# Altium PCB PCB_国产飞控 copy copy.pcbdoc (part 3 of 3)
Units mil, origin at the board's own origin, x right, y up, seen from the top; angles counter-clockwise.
Board outline 2782.5 x 2450 mil, 4 copper layers (Top Layer, Inner1, Inner2, Bottom Layer), stack 2.757 mil thick; 92 components, 104 nets, 474 pads, 149 vias.
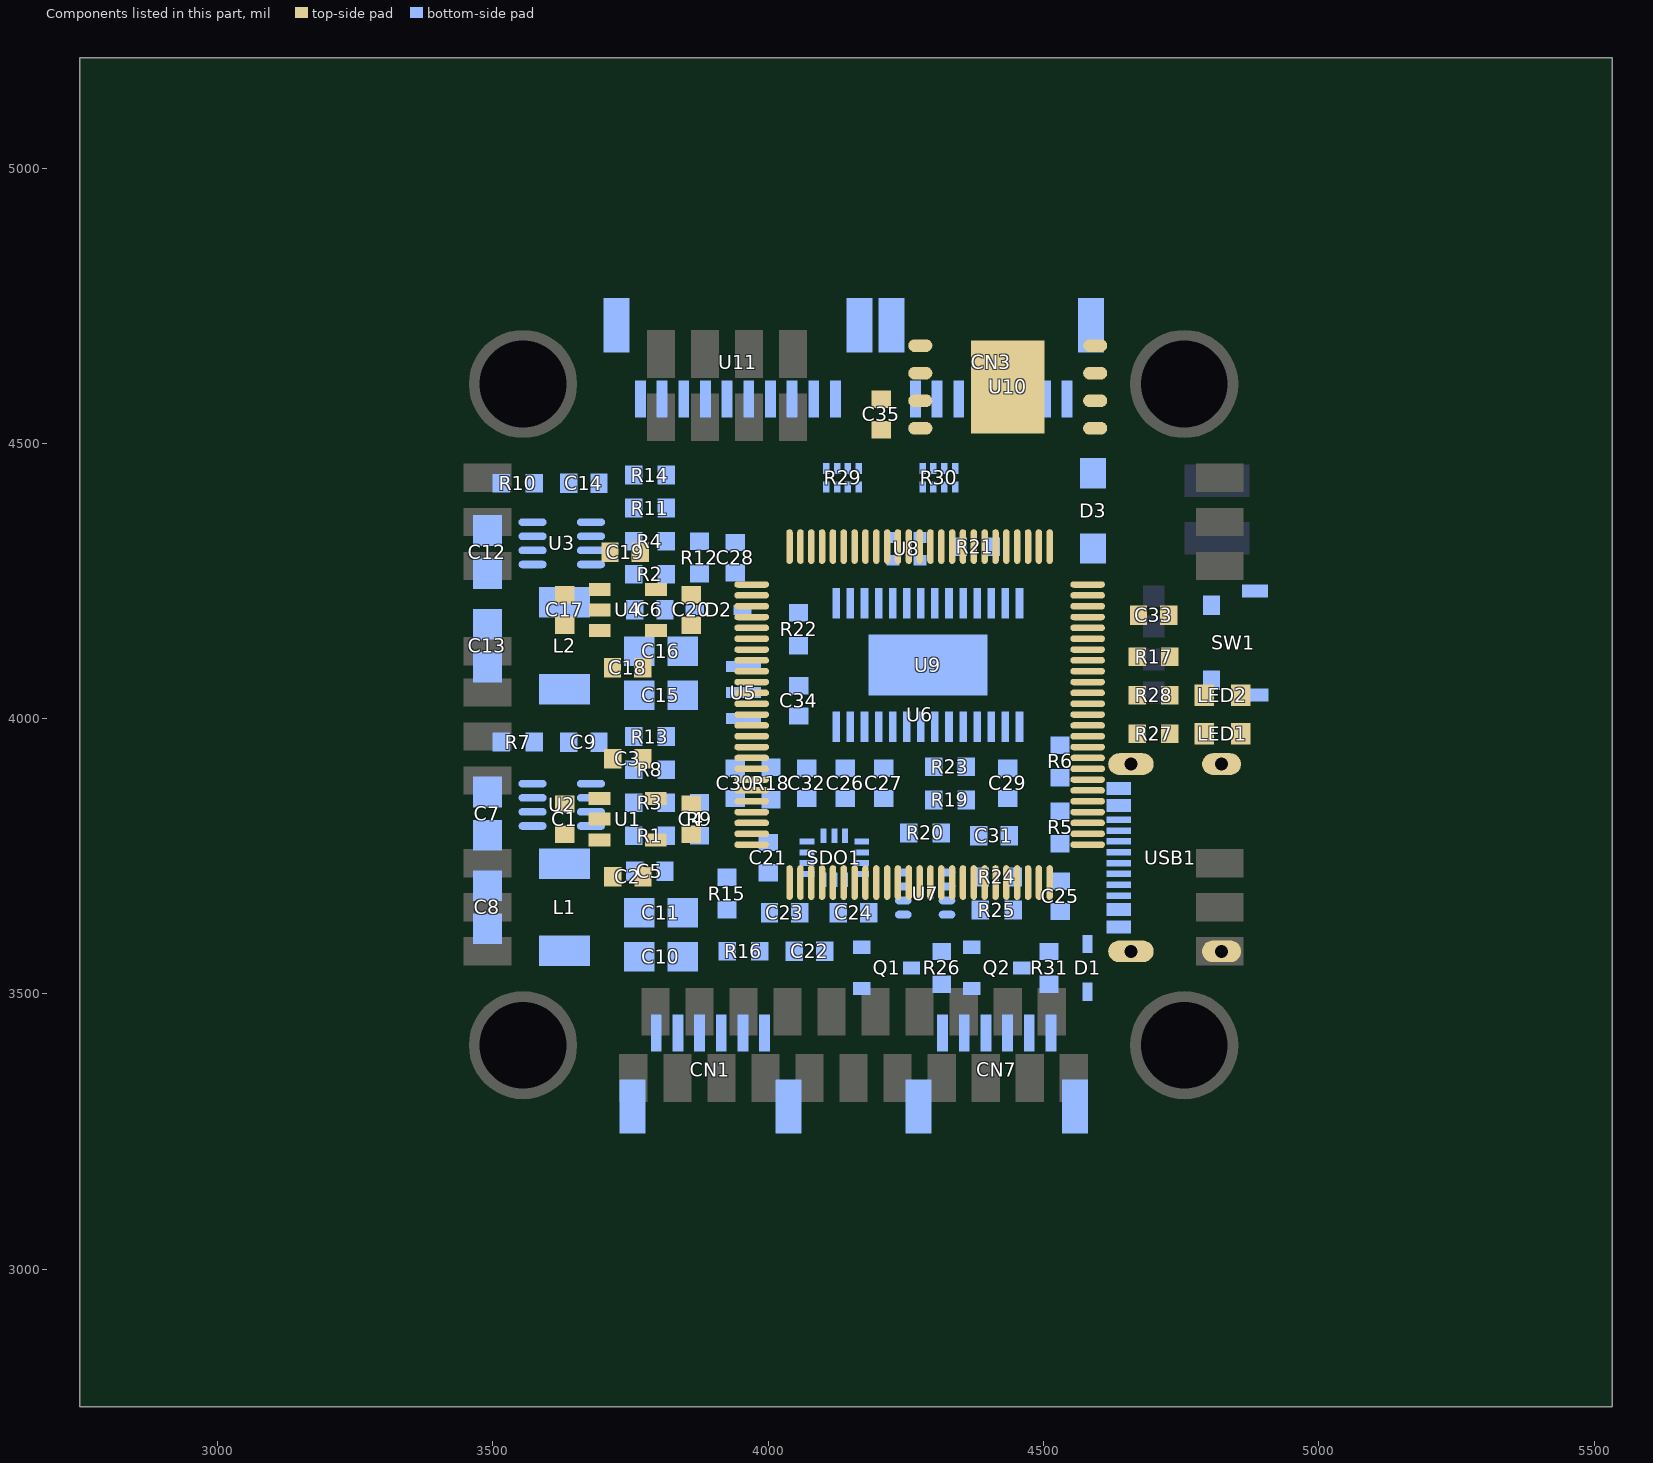
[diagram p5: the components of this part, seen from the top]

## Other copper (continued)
Inner2:
  region net SERVO2: 4358.07,4368.35 4358.07,4386.65 4366.62,4382.5 4366.62,4372.5
  region net SERVO1: 4398.07,4408.35 4398.07,4426.65 4406.62,4422.5 4406.62,4412.5
  region net GYRO_EXTI1: 4195.85,3760.57 4214.15,3760.57 4210,3769.12 4200,3769.12
  region net GYRO_EXTI1: 4490.76,4245.32 4477.82,4258.26 4474.71,4249.29 4481.79,4242.21
  region net +10V: 3757.18,3506.74 3744.24,3519.68 3749.43,3523.07 3760.57,3511.93
  region net UART4_RX: 3915.76,3794.68 3902.82,3781.74 3899.71,3790.71 3906.79,3797.79
  region net UART4_RX: 3880.76,4390.32 3867.82,4403.26 3864.71,4394.29 3871.79,4387.21
  region net 3V3-IMU: 3982.18,3718.26 3969.24,3705.32 3978.21,3702.21 3985.29,3709.29
  region net SERVO2: 4537.18,4031.74 4524.24,4044.68 4533.21,4047.79 4540.29,4040.71
  region net SERVO1: 4630.76,4029.68 4617.82,4016.74 4614.71,4025.71 4621.79,4032.79
  region net UART1_RX: 4642.18,4113.26 4629.24,4100.32 4638.21,4097.21 4645.29,4104.29
  region net UART1_TX: 4525.76,4105.32 4512.82,4118.26 4509.71,4109.29 4516.79,4102.21
  region net VBAT_ADC: 4220.76,3579.68 4207.82,3566.74 4206.46,3573.96 4213.54,3581.04
  region net VBAT_ADC: 3962.18,3613.26 3949.24,3600.32 3958.21,3597.21 3965.29,3604.29
  region net CURRENT1: 4260.76,3629.68 4247.82,3616.74 4244.71,3625.71 4251.79,3632.79
  region net CURRENT1: 3798.07,4468.35 3798.07,4486.65 3806.62,4482.5 3806.62,4472.5
  region net +10V: 3748.07,4623.35 3748.07,4641.65 3755,4640.37 3755,4624.63
  region net VDD: 4685.85,4250.57 4704.15,4250.57 4700,4259.12 4690,4259.12
  region net VDD: 4620.85,4644.43 4639.15,4644.43 4635,4635.88 4625,4635.88
  region net LED: 3540.85,4229.43 3559.15,4229.43 3555,4220.88 3545,4220.88
  region net LED: 3540.85,3775.57 3559.15,3775.57 3555,3784.12 3545,3784.12
  region net +5V: 4025.85,4724.43 4044.15,4724.43 4042.87,4715.88 4027.13,4715.88
  region net +5V: 4090.85,4170.57 4109.15,4170.57 4107.87,4179.12 4092.13,4179.12
  region net +5V: 3655.85,3925.57 3674.15,3925.57 3672.87,3934.12 3657.13,3934.12
  region net +5V: 4530.23,4210.62 4511.93,4210.67 4516.06,4219.2 4526.14,4219.17
  region net +5V: 3713.25,4152.03 3731.55,4152.03 3730.27,4143.48 3714.53,4143.48
  region net 3V3-IMU: 4195.76,3629.68 4182.82,3616.74 4179.71,3625.71 4186.79,3632.79
  region net UART1_RX: 4265.85,3539.43 4284.15,3539.43 4280,3530.88 4270,3530.88
  region net UART1_TX: 4126.74,3464.16 4116.85,3479.56 4126.21,3480.79 4131.75,3472.18
  region net UART1_RX: 4207.18,3466.74 4194.24,3479.68 4203.21,3482.79 4210.29,3475.71
Bottom Layer:
  region net U3_8: 3553.2,4363.79 3590.6,4363.79 3579.77,4370.9 3564.03,4370.9
  region net R7_2: 3553.2,3888.79 3590.6,3888.79 3579.77,3900.9 3564.03,3900.9
  region net VDD: 4316.78,3662.54 4316.77,3676.88 4301.77,3674.7 4301.78,3664.7
  region net I2C_SDA: 4332.64,3688.13 4332.64,3702.47 4342.5,3700.3 4342.5,3690.3
  region net I2C_SDA: 4316.78,3688.13 4316.78,3702.47 4301.78,3700.3 4301.78,3690.3
  region net I2C_SCL: 4332.65,3713.73 4332.64,3728.06 4347.64,3725.9 4347.65,3715.9
  region net VDD: 4253.23,3688.13 4253.23,3702.47 4267.2,3700.3 4267.2,3690.3
  region net VDD: 4253.24,3651.27 4253.23,3636.94 4268.23,3639.1 4268.24,3649.1
  region net R29_5: 3954.84,4547.1 3974.53,4547.1 3969.7,4537.8 3959.7,4537.8
  region net R29_6: 3915.47,4547.1 3935.16,4547.1 3930.3,4537.2 3920.3,4537.2
  region net R29_7: 3876.1,4547.1 3895.79,4547.1 3890.9,4532.1 3880.9,4532.1
  region net CURRENT1: 3757.99,4547.1 3777.68,4547.1 3772.8,4532.1 3762.8,4532.1
  region net UART4_RX: 3797.36,4547.1 3817.05,4547.1 3812.2,4532.1 3802.2,4532.1
  region net R29_8: 3836.73,4547.1 3856.42,4547.1 3851.6,4532.1 3841.6,4532.1
  region net 3V3-IMU: 4017.72,3705.5 4017.72,3730.5 4032.72,3723 4032.72,3713
  region net 3V3-IMU: 3982.28,3730 3982.28,3705 3970,3712.5 3970,3722.5
  region net 3V3-IMU: 3989.9,3704.19 4014.9,3704.19 4007.4,3689.19 3997.4,3689.19
  region net R13_2: 3857.99,3838.27 3888.6,3863.03 3861.69,3871.64 3849.38,3861.69
  region net +10V: 3888.6,3771.97 3857.99,3796.73 3849.38,3773.31 3861.69,3763.36
  region net R8_1: 3764.23,3890.49 3739.47,3921.1 3730.86,3894.19 3740.81,3881.88
  region net R13_2: 3830.53,3924.51 3798.78,3924.51 3806.83,3948.13 3822.57,3948.13
  region net R13_2: 3830.53,3921.1 3805.77,3890.49 3829.19,3881.88 3839.14,3894.19
  region net R7_1: 3590.53,3974.51 3590.53,3940.49 3614.15,3949.63 3614.15,3965.37
  region net R7_2: 3531.22,3970.9 3506.22,3940.49 3529.75,3931.92 3539.8,3944.14
  region net DP: 4547.01,3891.51 4526.67,3876.97 4544.47,3871.26 4552.72,3877.15
  region net D+: 4542.5,3968.03 4517.5,3968.03 4525,3983.03 4535,3983.03
  region net DN: 4547.01,3785.3 4547.01,3760.3 4549.7,3767.8 4549.7,3777.8
  region net D-: 4512.99,3833.49 4533.33,3848.03 4515.53,3853.74 4507.28,3847.85
  region net R3_1: 3764.23,3830.49 3739.47,3861.1 3733.52,3836.86 3744.07,3825.13
  region net VBAT: 3824.08,3830.49 3798.78,3860.66 3790.28,3834.03 3800.45,3821.91
  region net R1_1: 3739.47,3773.9 3764.23,3804.51 3743.27,3810.67 3732.72,3798.94
  region net R1_2: 3798.78,3770.49 3830.53,3770.49 3822.57,3746.87 3806.83,3746.87
  region net +10V: 3864.08,3674.07 3824.71,3674.07 3836.53,3697.7 3852.27,3697.7
  region net +10V: 3849.84,3620.93 3816.62,3642.04 3807.12,3620.09 3820.73,3611.44
  region net +10V: 3762.76,3594.07 3793.38,3569.33 3802.01,3592.73 3789.69,3602.69
  region net +10V: 3737.87,3594.07 3737.87,3540.93 3702.44,3555.69 3702.44,3579.31
  region net R7_1: 3621.69,3975.22 3621.69,3939.78 3598.07,3949.63 3598.07,3965.37
  region net R7_1: 3621.69,3939.78 3653.19,3939.78 3645.27,3916.16 3629.53,3916.16
  region net VBAT: 3463.43,3680.09 3502.21,3724.63 3466.28,3737.32 3450.73,3719.47
  region net VBAT: 3516.57,3839.12 3516.57,3875.98 3540.2,3864.17 3540.2,3848.42
  region net VBAT: 3463.43,3894.63 3463.43,3839.12 3435,3855.09 3435,3878.71
  region net R1_2: 3828.31,3740.22 3796.81,3740.22 3806.83,3763.84 3822.57,3763.84
  region net L1_1: 3741.69,3740.22 3741.69,3704.78 3718.07,3714.63 3718.07,3730.37
  region net R12_2: 3676.26,4026.2 3676.26,4072.03 3711.69,4054.31 3711.69,4030.69
  region net U3_6: 3676.26,4183.68 3676.26,4217.19 3699.88,4205.37 3699.88,4189.63
  region net U3_6: 3649.68,4238.8 3610.32,4238.8 3622.13,4262.42 3637.87,4262.42
  region net R12_2: 3879.68,4188.54 3850.16,4188.54 3852.13,4164.92 3867.87,4164.92
  region net R12_2: 3855.32,4206.46 3883.43,4206.46 3882.87,4230.08 3867.13,4230.08
  region net +5V: 3969.84,4188.54 3936.57,4195.68 3919.71,4175.14 3938.04,4171.21
  region net R30_5: 4454.21,4547.11 4473.9,4547.11 4469.1,4536.6 4459.1,4536.6
  region net R30_6: 4414.84,4547.11 4434.53,4547.11 4429.7,4537.2 4419.7,4537.2
  region net R30_7: 4375.47,4547.11 4395.16,4547.11 4390.3,4537.8 4380.3,4537.8
  region net R30_8: 4336.1,4547.11 4355.79,4547.11 4350.9,4538.4 4340.9,4538.4
  region net UART4_RX: 4296.73,4547.11 4316.42,4547.11 4311.6,4544.1 4301.6,4544.1
  region net +10V: 3786.73,3442.9 3806.42,3462.89 3786.9,3476.74 3775.85,3465.52
  region net UART3_TX: 3885.15,3462.89 3865.47,3462.89 3870.3,3477.89 3880.3,3477.89
  region net SBUS: 3991.43,3462.89 4003.26,3440.87 4009.86,3460.29 4004.92,3469.49
  region net UART3_RX: 3904.84,3462.89 3924.52,3456.55 3933.87,3469.29 3923.17,3472.74
  region net VBUS: 4659.23,3846.06 4629.99,3841.98 4654.53,3834.45 4668.57,3841.59
  region net DN: 4659.23,3771.12 4659.23,3782.93 4665.5,3782 4665.5,3772
  region net DP: 4613.96,3763.24 4613.96,3751.43 4605.2,3752.3 4605.2,3762.3
  region net DN: 4659.23,3731.75 4659.23,3743.56 4664.8,3742.7 4664.8,3732.7
  region net DN: 4613.96,3743.56 4613.96,3731.75 4598.96,3732.7 4598.96,3742.7
  region net DP: 4613.96,3723.87 4613.96,3712.06 4598.96,3713 4598.96,3723
  region net VBUS: 4630.1,3653.02 4659.23,3648.19 4667.03,3651.95 4653.17,3659.46
  region net VDD: 4789.36,4218.2 4789.36,4193.2 4781.8,4200.7 4781.8,4210.7
  region net BOOT0: 4812.43,4087.57 4789.36,4087.57 4777.86,4102.57 4792,4102.57
  region net +10V: 3676.26,3551.2 3676.26,3597.03 3711.69,3579.31 3711.69,3555.69
  region net L1_1: 3649.68,3763.8 3610.32,3763.8 3622.13,3787.42 3637.87,3787.42
  region net L1_1: 3676.26,3708.68 3676.26,3742.18 3699.88,3730.37 3699.88,3714.63
  region net R11_2: 3798.78,4425.49 3830.53,4425.49 3822.57,4401.87 3806.83,4401.87
  region net R11_2: 3857.99,4313.27 3888.6,4338.03 3861.69,4346.64 3849.38,4336.69
  region net R12_2: 3857.99,4246.97 3892.01,4246.97 3882.87,4223.35 3867.13,4223.35
  region net U3_1: 3764.23,4365.49 3739.47,4396.1 3730.86,4369.19 3740.81,4356.88
  region net R11_2: 3830.53,4399.51 3798.78,4399.51 3806.83,4423.13 3822.57,4423.13
  region net R11_2: 3830.53,4396.1 3805.77,4365.49 3829.19,4356.88 3839.14,4369.19
  region net U3_2: 3590.53,4444.51 3590.53,4410.49 3614.15,4419.63 3614.15,4435.37
  region net U3_8: 3531.22,4440.9 3506.22,4410.49 3529.75,4401.92 3539.8,4414.14
  region net U3_3: 3764.23,4305.49 3739.47,4336.1 3733.52,4311.86 3744.07,4300.13
  region net VBAT: 3798.78,4309.34 3824.08,4339.51 3800.45,4348.09 3790.28,4335.97
  region net U3_4: 3739.47,4248.9 3764.23,4279.51 3743.27,4285.67 3732.72,4273.94
  region net C6_1: 3798.78,4245.49 3830.53,4245.49 3820.47,4221.87 3804.73,4221.87
  region net R12_2: 3872.13,4149.07 3840.32,4149.07 3852.13,4172.7 3867.87,4172.7
  region net R12_2: 3849.84,4095.93 3816.62,4117.04 3807.12,4095.09 3820.73,4086.44
  region net R12_2: 3762.76,4069.07 3793.38,4044.33 3802.01,4067.73 3789.69,4077.69
  region net R12_2: 3737.87,4069.07 3737.87,4015.93 3702.44,4030.69 3702.44,4054.31
  region net VBAT: 3463.43,4199.63 3463.43,4144.12 3430,4160.09 3430,4183.71
  region net VBAT: 3516.57,4314.12 3516.57,4350.98 3540.2,4339.17 3540.2,4323.42
  region net VBAT: 3463.43,4369.63 3463.43,4314.12 3430,4330.09 3430,4353.71
  region net C6_1: 3828.31,4215.22 3796.81,4215.22 3804.73,4238.84 3820.47,4238.84
  region net U3_6: 3741.69,4215.22 3741.69,4179.78 3718.07,4189.63 3718.07,4205.37
  region net U3_2: 3621.69,4445.22 3621.69,4409.78 3598.07,4419.63 3598.07,4435.37
  region net U3_2: 3621.69,4409.78 3653.19,4409.78 3642.87,4386.16 3627.13,4386.16
  region net I2C_SDA: 4369.47,3649.17 4384.01,3669.51 4369.65,3675.22 4363.76,3666.97
  region net VDD: 4457.2,3669.51 4432.2,3669.51 4439.7,3684.51 4449.7,3684.51
  region net I2C_SCL: 4369.47,3708.4 4369.47,3729.51 4354.47,3725.9 4354.47,3715.9
  region net VDD: 4450.1,3729.51 4428.78,3729.51 4432.6,3744.51 4442.6,3744.51
  region net VDD: 4432.2,3695.49 4457.2,3695.49 4449.7,3680.49 4439.7,3680.49
  region net VBAT_ADC: 4000.53,3565 4000.53,3590 4015.53,3582.5 4015.53,3572.5
  region net VBAT_ADC: 3968.78,3574.35 3983.57,3594.51 3969.11,3600.16 3963.13,3592
  region net VDD: 4052.28,3865.3 4052.28,3840.3 4037.28,3847.8 4037.28,3857.8
  region net VDD: 4450.1,3805.22 4425.1,3805.22 4432.6,3820.22 4442.6,3820.22
  region net VDD: 4425.1,3769.78 4450.1,3769.78 4442.6,3754.78 4432.6,3754.78
  region net VDD: 3957.72,3840.3 3957.72,3865.3 3972.72,3857.8 3972.72,3847.8
  region net VDD: 4425.1,3839.19 4450.1,3839.19 4442.6,3824.19 4432.6,3824.19
  region net VDD: 3957.72,4304.31 3957.72,4325 3972.72,4317.5 3972.72,4307.5
  region net VDD: 4547.72,3689.31 4547.72,3712.28 4562.72,3691.85 4562.72,3677.71
  region net VBAT_ADC: 4031.69,3590 4031.69,3565 4016.69,3572.5 4016.69,3582.5
  region net VBUS: 4571.04,3607.34 4588.96,3607.34 4587.87,3622.5 4572.13,3622.5
  region net +5V: 4571.04,3487.66 4588.96,3487.66 4587.87,3472.5 4572.13,3472.5
  region net +5V: 4588.96,3487.66 4588.96,3520.93 4612.58,3512.17 4612.58,3496.43
  region net BEEPER: 4492.99,3567.01 4492.99,3592.01 4477.99,3601.58 4477.99,3587.44
  region net Q2_1: 4492.99,3522.6 4492.99,3501.97 4477.99,3505.1 4477.99,3515.1
  region net UART1_RX: 4297.99,3512.01 4297.99,3533.72 4282.99,3546.58 4282.99,3532.44
  region net VDD: 4327.5,3593.03 4302.5,3593.03 4310,3607.5 4320,3607.5
  region net U9_19: 4343.78,3929.51 4366.5,3929.51 4359,3944.51 4349,3944.51
  region net +5V: 4315.3,3929.51 4290.3,3929.51 4297.8,3944.51 4307.8,3944.51
  region net +5V: 4284.47,3915 4284.47,3895.49 4269.47,3897.5 4269.47,3907.5
  region net OSD_IN_CAM: 4042.5,4116.97 4067.5,4116.97 4060,4101.97 4050,4101.97
  region net +5V: 4420.53,4325 4420.53,4300 4435.53,4307.5 4435.53,4317.5
  region net AT_CS: 4353.18,4295.49 4329.47,4303.43 4320.91,4290.48 4331.5,4286.93
  region net C27_1: 4284.47,3840 4284.47,3865 4269.47,3857.5 4269.47,3847.5
  region net OSD_OUT_VTX: 4347.2,3835.49 4372.2,3835.49 4364.7,3827.2 4354.7,3827.2
  region net U9_22: 4051.01,4020.69 4072.72,4008.29 4079.09,4021.92 4070.09,4027.06
  region net OSD_IN_CAM: 4067.5,4075.81 4042.5,4075.81 4050,4090.81 4060,4090.81
  region net C27_1: 4192.28,3867.4 4192.28,3842.4 4177.28,3849.9 4177.28,3859.9
  region net C27_1: 4227.72,3840 4227.72,3865 4242.72,3857.5 4242.72,3847.5
  region net C27_2: 4212.9,3925.81 4192.28,3925.81 4195.4,3940.81 4205.4,3940.81
  region net C27_1: 4157.72,3842.4 4157.72,3867.4 4172.72,3859.9 4172.72,3849.9
  region net C26_2: 4135.88,3925.81 4157.72,3913.64 4164.18,3927.21 4155.1,3932.27
  region net U9_19: 4347.09,3957.73 4360.87,3957.73 4359,3942.73 4349,3942.73
  region net +5V: 4295.91,3957.73 4309.69,3957.73 4307.8,3942.73 4297.8,3942.73
  region net U9_22: 4284.1,4012.85 4270.32,4012.85 4272.2,4015.3 4282.2,4015.3
  region net +5V: 4219.13,3957.73 4232.91,3957.73 4231,3946.5 4221,3946.5
  region net C27_2: 4193.54,3957.73 4207.32,3957.73 4205.4,3942.73 4195.4,3942.73
  region net C26_2: 4167.95,3957.73 4181.73,3957.73 4179.8,3944.9 4169.8,3944.9
  region net AT_MISO: 4386.46,4237.26 4372.68,4237.26 4374.6,4252.26 4384.6,4252.26
  region net AT_SCK: 4360.87,4237.26 4347.09,4237.26 4349,4252.26 4359,4252.26
  region net AT_MOSI: 4335.28,4237.26 4321.5,4237.26 4323.4,4252.26 4333.4,4252.26
  region net AT_CS: 4309.69,4237.26 4295.91,4237.26 4297.8,4249.7 4307.8,4249.7
  region net U9_6: 4258.5,4237.26 4244.72,4237.26 4246.6,4252.26 4256.6,4252.26
  region net U9_5: 4232.91,4237.26 4219.13,4237.26 4221,4246.5 4231,4246.5
  region net +5V: 4167.95,4182.14 4181.73,4182.14 4179.8,4177.3 4169.8,4177.3
  region net U9_5: 4236.3,4319.31 4214.57,4331.67 4208.18,4318.05 4217.19,4312.92
  region net GND: 4265.92,4319.31 4263.78,4339 4250.82,4319.36 4252.21,4306.59
  region net U9_6: 4285.59,4277.97 4263.78,4290.19 4257.33,4276.61 4266.4,4271.53
  region net GND: 4216.45,4297.66 4238.19,4285.32 4244.58,4298.94 4235.56,4304.06
  region net HEXT_IN: 3923.5,4104.54 3923.5,4084.86 3908.5,4089.7 3908.5,4099.7
  region net HEXT_OUT: 3923.5,4010.14 3923.5,3990.46 3908.5,3995.3 3908.5,4005.3
  region net Q2_1: 4385.5,3521.9 4385.5,3498.3 4400.5,3505.1 4400.5,3515.1
  region net SBUS: 4157.3,3521.9 4182.3,3521.9 4174.8,3532.7 4164.8,3532.7
  region net UART1_RX: 4276,3559 4276,3535.7 4291,3524.43 4291,3538.57
  region net 3V3-IMU: 4170.22,3629.78 4195.22,3629.78 4198.54,3621.04 4187.93,3617.5
  region net 3V3-IMU: 4194.68,3665.22 4169.68,3665.22 4160.07,3680.22 4174.23,3680.22
  region net 3V3-IMU: 4014.9,3665.22 3989.9,3665.22 3997.4,3680.22 4007.4,3680.22
  region net GYRO_MOSI: 4145.19,3800.65 4134.17,3800.65 4134.7,3807.2 4144.7,3807.2
  region net GYRO_SCK: 4125.51,3800.65 4114.49,3800.65 4115,3815.65 4125,3815.65
  region net GYRO_CS1: 4094.8,3788.6 4105.82,3800.65 4098.54,3806.04 4091.62,3798.81
  region net GYRO_EXTI2: 4057.03,3743.17 4057.03,3732.15 4054.8,3732.7 4054.8,3742.7
  region net 3V3-IMU: 4057.03,3723.48 4057.03,3712.46 4042.03,3713 4042.03,3723
  region net 3V3-IMU: 4145.19,3694.35 4145.19,3714.62 4160.19,3694.22 4160.19,3680.09
  region net GYRO_EXTI1: 4182.97,3712.46 4182.97,3723.48 4195.5,3723 4195.5,3713
  region net GYRO_MISO: 4182.5,3782.54 4157.5,3782.54 4165,3797.54 4175,3797.54
  region net VBAT: 4613.6,4418.2 4613.6,4473.4 4654.94,4461.28 4654.94,4433.72
  region net VBAT: 4613.6,4473.4 4566.4,4473.4 4576.22,4514.74 4603.78,4514.74
  region net R30_5: 4345.43,4444.39 4345.43,4464.27 4360.43,4459.3 4360.43,4449.3
  region net R30_6: 4325.75,4464.27 4313.94,4464.27 4314.8,4467.3 4324.8,4467.3
  region net R30_7: 4306.06,4464.27 4294.25,4464.27 4295.2,4477.7 4305.2,4477.7
  region net R30_8: 4286.38,4464.27 4274.57,4464.27 4275.5,4479.27 4285.5,4479.27
  region net SERVO1: 4345.43,4430 4345.43,4410.73 4360.43,4412.5 4360.43,4422.5
  region net SERVO2: 4325.75,4410.73 4313.94,4410.73 4314.8,4397.7 4324.8,4397.7
  region net SERVO3: 4306.06,4410.73 4294.25,4410.73 4295.2,4397.7 4305.2,4397.7
  region net SERVO4: 4286.38,4410.73 4274.57,4418.29 4266.24,4405.81 4274.86,4400.29
  region net R29_5: 4170.43,4464.27 4158.62,4464.27 4159.5,4479.27 4169.5,4479.27
  region net R29_6: 4150.75,4464.27 4138.94,4464.27 4139.8,4479.27 4149.8,4479.27
  region net R29_7: 4131.06,4464.27 4119.25,4464.27 4120.2,4467.3 4130.2,4467.3
  region net R29_8: 4099.57,4464.27 4099.57,4444.39 4084.57,4449.3 4084.57,4459.3
  region net MOTOR1: 4170.43,4430.61 4170.43,4410.73 4181.8,4415.7 4181.8,4425.7
  region net MOTOR2: 4150.75,4410.73 4138.94,4410.73 4139.8,4407.7 4149.8,4407.7
  region net MOTOR3: 4131.06,4410.73 4119.25,4410.73 4120.2,4397.3 4130.2,4397.3
  region net MOTOR4: 4111.38,4410.73 4099.57,4410.73 4100,4395.73 4110,4395.73
  region net U6_37: 4239.47,3775.49 4257.5,3775.49 4250,3760.49 4240,3760.49
  region net U6_14: 3987.99,3913.49 4008.33,3928.03 3990.53,3933.74 3982.28,3927.85
  region net VDD: 3987.99,3865.3 3987.99,3840.3 3972.99,3847.8 3972.99,3857.8
  region net VDD: 4022.01,3840.3 4022.01,3865.3 4037.01,3857.8 4037.01,3847.8
  region net VBAT_ADC: 3937.73,3636.97 3912.73,3636.97 3933.16,3621.97 3947.3,3621.97
  region net VBAT: 3907.99,3728.03 3907.99,3705 3892.99,3712.5 3892.99,3722.5
  region net R13_2: 3798.78,3950.49 3830.53,3950.49 3822.57,3926.87 3806.83,3926.87
  region net I2C_SDA: 4306.73,3440.88 4318.58,3462.89 4305.09,3469.48 4300.14,3460.29
  region net I2C_SCL: 4365.79,3462.89 4346.1,3462.89 4350,3467.38 4360,3467.5
  region net UART1_RX: 4397.64,3395.96 4385.47,3417.8 4379.01,3398.58 4384.07,3389.5
  region net +5V: 4523.26,3409.71 4523.26,3449.08 4536.9,3437.27 4536.9,3421.53
  region net UART1_TX: 4424.84,3395.96 4444.52,3395.96 4439.7,3380.96 4429.7,3380.96
  region net SWDCLK: 4680.31,4162.55 4684.54,4187.19 4671.24,4198.33 4669.17,4186.26
  region net VDD: 4719.69,4235 4719.69,4210 4734.69,4217.5 4734.69,4227.5
  region net SWDIO: 4680.31,4095 4680.31,4120 4675,4112.5 4675,4102.5
  region net VBAT: 4755.94,4402.97 4755.94,4462.03 4714.61,4446.28 4714.61,4418.72
  region net I2C_SDA: 4283.07,3458.35 4283.07,3476.65 4291.62,3472.5 4291.62,3462.5
  region net I2C_SCL: 4364.34,3459.65 4346.04,3459.21 4350.39,3450.77 4360.39,3451.01
  region net UART1_RX: 4185.85,3459.43 4204.15,3459.43 4200,3450.88 4190,3450.88
  region net UART1_TX: 4105.85,3459.43 4124.15,3459.43 4120,3450.88 4110,3450.88
  region net UART1_RX: 4287.18,3548.26 4274.24,3535.32 4283.21,3532.21 4290.29,3539.29
  region net UART1_RX: 4266.93,3538.35 4266.93,3556.65 4260.2,3552.5 4260.2,3542.5
  region net BEEPER: 4487.18,3598.26 4474.24,3585.32 4483.21,3582.21 4490.29,3589.29
  region net VDD: 4030.85,3869.43 4049.15,3869.43 4045,3860.88 4035,3860.88
  region net 3V3-IMU: 4195.76,3629.68 4182.82,3616.74 4179.71,3625.71 4186.79,3632.79
  region net +5V: 4530.23,4210.62 4511.93,4210.67 4516.1,4219.2 4526.1,4219.17
  region net VDD: 4466.93,3813.35 4466.93,3831.65 4458.38,3827.5 4458.38,3817.5
  region net VDD: 4280.85,3639.43 4299.15,3639.43 4295,3632.5 4285,3632.5
  region net VDD: 4280.85,3655.57 4299.15,3655.57 4295,3664.12 4285,3664.12
  region net VDD: 4283.97,3636.89 4280.22,3654.81 4272.69,3649.1 4274.78,3639.1
  region net +5V: 4575.76,3455.32 4562.82,3468.26 4557.68,3461.32 4568.82,3450.18
  region net +5V: 4568.7,3477.95 4586.16,3472.44 4587.87,3480.86 4572.13,3485.83
  region net +5V: 4750.85,3649.43 4769.15,3649.43 4767.87,3640.88 4752.13,3640.88
  region net +5V: 4110.45,4156.2 4104.94,4173.66 4114.27,4172.5 4117.42,4162.5
  region net +5V: 4091.93,4153.35 4091.93,4171.65 4083.38,4169.39 4083.38,4155.61
  region net VDD: 4573.15,3689.56 4563.26,3674.16 4558.25,3682.18 4563.79,3690.79
  region net VDD: 3976.93,4303.35 3976.93,4321.65 3968.38,4317.5 3968.38,4307.5
  region net OSD_IN_CAM: 4045.85,4105.57 4064.15,4105.57 4060,4114.12 4050,4114.12
  region net OSD_IN_CAM: 4045.85,4089.43 4064.15,4089.43 4060,4080.88 4050,4080.88
  region net UART4_RX: 4215.85,4445.57 4234.15,4445.57 4230,4454.12 4220,4454.12
  region net +5V: 3900.85,4145.57 3919.15,4145.57 3917.87,4154.12 3902.13,4154.12
  region net SWDIO: 4642.18,4153.26 4629.24,4140.32 4638.21,4137.21 4645.29,4144.29
  region net SWDCLK: 4655.85,4294.43 4674.15,4294.43 4670,4285.88 4660,4285.88
  region net CURRENT1: 3790.76,4489.68 3777.82,4476.74 3774.71,4485.71 3781.79,4492.79
  region net VBAT_ADC: 3950.61,3624.69 3937.83,3611.58 3934.61,3620.52 3941.59,3627.68
  region net VBAT_ADC: 3962.19,3613.11 3949.08,3600.33 3958.02,3597.11 3965.18,3604.09
  region net 3V3-IMU: 3978.07,3708.35 3978.07,3726.65 3986.62,3722.5 3986.62,3712.5
  region net UART4_RX: 3870.85,4410.57 3889.15,4410.57 3885,4419.12 3875,4419.12
  region net OSD_OUT_VTX: 4362.18,3816.74 4349.24,3829.68 4356.16,3830.74 4363.24,3823.66
  region net U6_14: 3923.07,3948.35 3923.07,3966.65 3931.62,3962.5 3931.62,3952.5
  region net HEXT_IN: 3907.18,4081.74 3894.24,4094.68 3903.21,4097.79 3910.29,4090.71
  region net HEXT_OUT: 3909.5,3989.84 3906.41,4007.88 3915.52,4005.3 3917.23,3995.3
  region net +5V: 4273.07,3893.35 4273.07,3911.65 4281.62,3907.5 4281.62,3897.5
  region net +5V: 4265.76,3914.68 4252.82,3901.74 4249.71,3910.71 4256.79,3917.79
  region net VBAT: 3883.07,3708.35 3883.07,3726.65 3891.62,3722.5 3891.62,3712.5
  region net VBAT: 3797.18,3816.8 3784.17,3829.68 3791.09,3834.85 3802.29,3823.77
  region net VBAT: 3797.18,4353.2 3784.17,4340.32 3791.09,4335.15 3802.29,4346.23
  region net VBAT: 3420.85,3809.43 3439.15,3809.43 3441.81,3800.88 3418.19,3800.88
  region net VBAT: 3420.85,3825.57 3439.15,3825.57 3441.81,3834.12 3418.19,3834.12
  region net VBAT: 3438.07,4162.75 3438.07,4181.05 3446.62,4183.71 3446.62,4160.09
  region net VBAT: 3420.85,4179.97 3439.15,4179.97 3441.81,4188.52 3418.19,4188.52
  region net VBAT: 3420.85,4163.83 3439.15,4163.83 3441.81,4155.28 3418.19,4155.28
  region net VBAT: 3420.85,4389.43 3439.15,4389.43 3441.81,4380.88 3418.19,4380.88
  region net U6_37: 4235.85,3760.57 4254.15,3760.57 4250,3769.12 4240,3769.12
  region net I2C_SDA: 4275.85,3744.43 4294.15,3744.43 4290,3735.88 4280,3735.88
  region net I2C_SCL: 4335.85,3744.43 4354.15,3744.43 4350,3735.88 4340,3735.88
  region net UART3_RX: 3986.93,3513.35 3986.93,3531.65 3980,3527.5 3980,3517.5
  region net UART3_TX: 3915.76,3510.32 3902.82,3523.26 3899.71,3514.29 3906.79,3507.21
  region net +10V: 3757.18,3508.26 3744.24,3495.32 3751.18,3490.18 3762.32,3501.32
  region net +10V: 3735.85,3515.57 3754.15,3515.57 3752.87,3524.12 3737.13,3524.12
  region net SBUS: 4167.18,3548.26 4154.24,3535.32 4163.21,3532.21 4170.29,3539.29
  region net SBUS: 4146.93,3538.35 4146.93,3556.65 4138.38,3552.5 4138.38,3542.5
  region net BB: 4466.93,3538.35 4466.93,3556.65 4460.25,3552.5 4460.25,3542.5
  region net D+: 4480.85,4159.43 4499.15,4159.43 4495,4150.88 4485,4150.88
  region net D-: 4455.85,4109.43 4474.15,4109.43 4470,4100.88 4460,4100.88
  region net GYRO_EXTI1: 4195.85,3744.43 4214.15,3744.43 4210,3735.88 4200,3735.88
  region net GYRO_EXTI2: 4030.85,3814.43 4049.15,3814.43 4045,3805.88 4035,3805.88
  region net GYRO_MISO: 4160.85,3794.43 4179.15,3794.43 4175,3785.88 4165,3785.88
  region net GYRO_CS1: 4078.07,3793.35 4078.07,3811.65 4086.62,3807.5 4086.62,3797.5
  region net GYRO_SCK: 4108.7,3812.05 4126.16,3817.56 4125,3808.23 4115,3805.08
  region net GYRO_MOSI: 4198.15,3829.56 4188.26,3814.16 4183.25,3822.18 4188.79,3830.79
  region net SERVO1: 4381.93,4408.35 4381.93,4426.65 4373.38,4422.5 4373.38,4412.5
  region net SERVO2: 4345.51,4388.85 4339.3,4371.62 4332.49,4377.93 4336.24,4388.33
  region net SERVO3: 4292.18,4376.74 4279.24,4389.68 4288.21,4392.79 4295.29,4385.71
  region net SERVO4: 4257.18,4376.74 4244.24,4389.68 4253.21,4392.79 4260.29,4385.71
  region net MOTOR1: 4200.85,4385.57 4219.15,4385.57 4215,4392.5 4205,4392.5
  region net MOTOR2: 4175.76,4389.68 4162.82,4376.74 4159.71,4385.71 4166.79,4392.79
  region net MOTOR3: 4127.94,4379.35 4143.34,4389.24 4135.32,4394.25 4126.71,4388.71
  region net MOTOR4: 4095.85,4385.57 4114.15,4385.57 4110,4394.12 4100,4394.12
  region net BOOT0: 4787.18,4113.26 4774.24,4100.32 4783.21,4097.21 4790.29,4104.29
  region net AT_MOSI: 4338.33,4248.58 4320.11,4250.35 4323.4,4241.44 4333.4,4240.48
  region net AT_MISO: 4388.96,4249.21 4370.65,4249.65 4374.6,4241.01 4384.6,4240.77
  region net AT_SCK: 4415.76,4269.68 4402.82,4256.74 4399.71,4265.71 4406.79,4272.79
  region net AT_CS: 4307.18,4256.74 4294.24,4269.68 4303.21,4272.79 4310.29,4265.71
  region net AT_CS: 4290.71,4246.07 4306.87,4254.67 4307.8,4245.49 4297.8,4240.17
  region net BOX_MOSI: 4491.93,4448.35 4491.93,4466.65 4483.38,4462.5 4483.38,4452.5
  region net BOX_MOSI: 4433.07,4448.35 4433.07,4466.65 4441.62,4462.5 4441.62,4452.5

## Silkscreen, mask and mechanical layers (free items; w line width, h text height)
Top Silkscreen Layer:
  drawing of 21 lines, arcs and shapes, not listed
  text "10V" at 3835,4482.5 h26.77 r180
  text "CAM" at 3925,4482.5 h26.77 r180
  text "GND" at 4005,4482.5 h26.77 r180
  text "5V" at 4065,4482.5 h26.77 r180
  text "GND 5V LED" at 3555,4472.5 h26.77 r270
  text "R4" at 3825,4432.5 h26.77 r180
  text "T4" at 3910,4432.5 h26.77 r180
  text "GND" at 4005,4432.5 h26.77 r180
  text "5V" at 4065,4432.5 h26.77 r180
  text "SHEEPFINDER" at 4160,4422.5 h59.05
  text "V1.1   2024.1" at 4210,4357.5 h59.05
  text "LED 5V GND" at 4755,4247.5 h26.77 r90
  text "MCU" at 3730.31,4237.5 h26.77 r270
  text "T8 R8 GND 5V" at 3555,4137.5 h26.77 r270
  text "AT32F435" at 4135,4127.5 h39.37
  text "IMU" at 3734.7,3842.5 h26.77 r270
  text "JLCJLCJLCJLC" at 4085,3832.5 h39.37
  text "LED 5V GND" at 3555,3767.5 h26.77 r270
  text "VTX" at 3760,3582.5 h26.77
  text "5V" at 3855,3582.5 h26.77
  text "T2" at 3925,3582.5 h26.77
  text "R2" at 4005,3582.5 h26.77
  text "T1" at 4085,3582.5 h26.77
  text "R1" at 4160,3582.5 h26.77
  text "SDA" at 4225,3582.5 h26.77
  text "SCL" at 4315,3582.5 h26.77
  text "GND" at 4400,3582.5 h26.77
  text "5V" at 4500,3582.5 h26.77
  text "GND 5V LED" at 4755,3542.5 h26.77 r90
  text "10V" at 3725,3532.5 h26.77
  text "GND" at 3800,3532.5 h26.77
  text "T3" at 3890,3532.5 h26.77
  text "R3" at 3965,3532.5 h26.77
  text "GND" at 4035,3532.5 h26.77
  text "5V" at 4125,3532.5 h26.77
  text "SBUS" at 4185,3532.5 h26.77
  text "5V" at 4300,3532.5 h26.77
  text "LED" at 4365,3532.5 h26.77
  text "BB-" at 4445,3532.5 h26.77
  text "BB+" at 4535,3532.5 h26.77
Bottom Silkscreen Layer:
  lines w3.94 net S$244950: 4090,3287.5 4140,3287.5 ; 4170,3367.5 4220,3367.5
  lines w3.94 net S$244954: 4095,3277.5 4090,3277.5 4080,3287.5 4090,3297.5 4095,3297.5 ; 4215,3357.5 4220,3357.5 4230,3367.5 4220,3377.5 4215,3377.5
  lines w31.5: 3397.13,3407.11 3397.13,4607.89 cw(c3554.61,4607.89) 3554.61,4765.37 4755.39,4765.37 cw(c4755.39,4607.89) 4912.87,4607.89 4912.87,3407.11 cw(c4755.39,3407.11) 4755.39,3249.63 3554.61,3249.63 cw(c3554.61,3407.11) 3397.13,3407.11
  text "GND" at 4020,4542.5 h26.77 r90
  text "GND" at 4060,4542.5 h26.77 r90
  text "BAT" at 4100,4542.5 h26.77 r90
  text "BAT" at 4140,4542.5 h26.77 r90
  text "GND" at 4520,4542.5 h26.77 r90
  text "BAT" at 4560,4542.5 h26.77 r90
  text "CC" at 3780,4537.5 h26.77 r90
  text "R4" at 3820,4537.5 h26.77 r90
  text "M4" at 3860,4537.5 h26.77 r90
  text "M3" at 3900,4537.5 h26.77 r90
  text "M2" at 3940,4537.5 h26.77 r90
  text "M1" at 3980,4537.5 h26.77 r90
  text "NC" at 4280,4537.5 h26.77 r90
  text "R4" at 4320,4537.5 h26.77 r90
  text "S4" at 4360,4537.5 h26.77 r90
  text "S3" at 4400,4537.5 h26.77 r90
  text "S2" at 4440,4537.5 h26.77 r90
  text "S1" at 4480,4537.5 h26.77 r90
  text "+" at 4730,4407.5 h70.87
  text "-" at 4735,4352.5 h70.87 r90
  text "3V3" at 4670,4207.5 h26.77
  text "5V" at 3645,4152.5 h26.77 r90
  text "SWDCLK" at 4670,4152.5 h26.77
  text "SWDIO" at 4670,4092.5 h26.77
  text "GND" at 4670,4032.5 h26.77
  text "BOOT" at 4890,3972.5 h26.77
  text "10V" at 3645,3687.5 h26.77 r90
  text "V" at 3790,3467.5 h26.77
  text "0" at 3805,3467.5 h26.77
  text "1" at 3815,3467.5 h26.77
  text "G" at 3845,3467.5 h26.77
  text "3" at 3875,3467.5 h26.77
  text "T" at 3890,3467.5 h26.77
  text "3" at 3915,3467.5 h26.77
  text "R" at 3930,3467.5 h26.77
  text "G" at 3965,3467.5 h26.77
  text "S" at 3995,3467.5 h26.77
  text "S" at 4015,3467.5 h26.77
  text "D" at 4125,3432.5 h26.77
  text "C" at 4155,3432.5 h26.77
  text "1" at 4175,3432.5 h26.77
  text "R" at 4195,3432.5 h26.77
  text "1" at 4215,3432.5 h26.77
  text "T" at 4235,3432.5 h26.77
  text "G" at 4260,3432.5 h26.77
  text "V" at 4285,3432.5 h26.77
  text "5" at 4300,3432.5 h26.77
  text "GPS" at 4235,3387.5 h26.77
  text "DJI" at 4135,3302.5 h26.77
Mechanical Layer:
  lines w0.1: 3334.12,4786.62 3534.12,4586.62 ccw(c3554.86,4607.64) 3575.88,4628.38 3375.88,4828.38 ccw(c3355.14,4807.36) 3334.12,4786.62 ; 3339.12,3233.38 ccw(c3360.14,3212.64) 3380.88,3191.62 3575.88,3386.62 ccw(c3554.86,3407.36) 3534.12,3428.38 3339.12,3233.38 ; 4734.12,3386.62 4929.12,3191.62 ccw(c4949.86,3212.64) 4970.88,3233.38 4775.88,3428.38 ccw(c4755.14,3407.36) 4734.12,3386.62 ; 4734.12,4628.38 4934.12,4828.38 cw(c4954.86,4807.36) 4975.88,4786.62 4775.88,4586.62 cw(c4755.14,4607.64) 4734.12,4628.38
